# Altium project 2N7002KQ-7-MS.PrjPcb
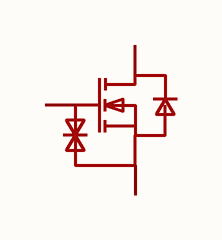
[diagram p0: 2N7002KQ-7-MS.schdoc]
1 sheet, 1 parts. Net scope: global (net labels, ports and power ports of the same name join across sheets).

## Sheet 2N7002KQ-7-MS.schdoc
size 127 x 101 mm

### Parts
Q?  2n7002kq-7-ms  [SOT-23-3_L2.9-W1.3-P0.95-LS2.4-BR]  (value not drawn)

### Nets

Not connected (* = marked no-connect by the designer): Q? 1(G) 2(S) 3(D)

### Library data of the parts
Q? = 2n7002kq-7-ms: 类型:1个N沟道;漏源电压(Vdss):60V;连续漏极电流(Id):300mA;导通电阻(RDS(on)@Vgs,Id):2.2Ω@10V,300mA;功率(Pd):350mW;阈值电压(Vgs(th)@Id):1.6V@250uA;; Manufacturer: MSKSEMI(美森科); AddInBom: yes; ModelId: c62791f0466c4ae2a892c056b845b0ca; ModelName: SOT-23-3P_L2.9-W1.3-H1.0-LS2.4-P0.95; ModelTransform: 98.425,114.173,0,180,0,0,0.0005,-0.0005,0; Type: 1个N沟道; Drain Source Voltage (Vdss): 60V; Power Dissipation (Pd): 350mW; Input Capacitance (Ciss@Vds): 38pF@30V; Reverse Transfer Capacitance (Crss@Vds): 12pF@30V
